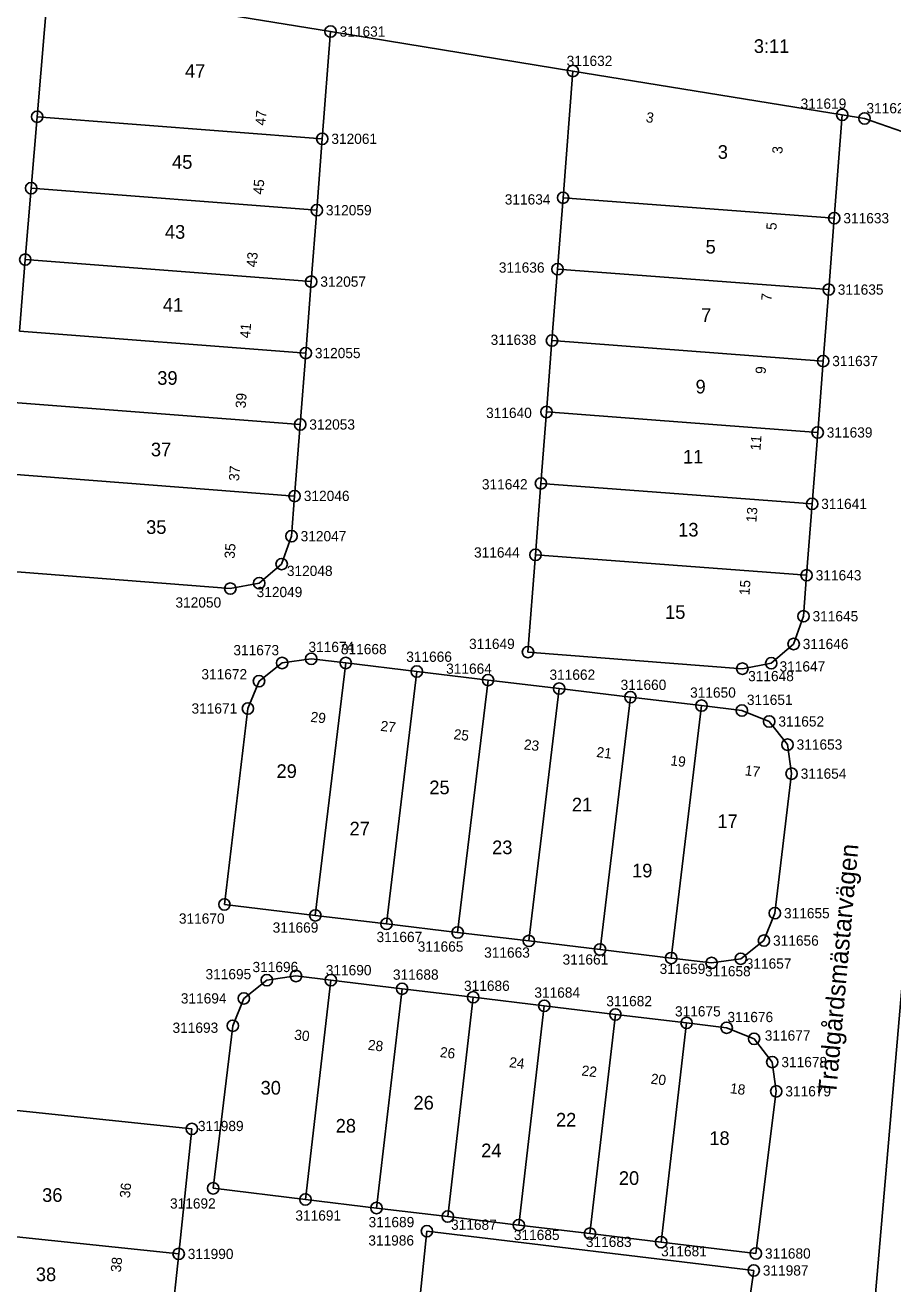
# Model space of a CAD drawing. Extents: x 141995 to 152570, y 6580184 to 6586000.
# Drawn here: x 142296 to 142372.2, y 6585066.5 to 6585177.1 of the extents above; entities that cross this region are included whole.
import ezdxf

# ---------------------------------------------------------------- set-up
doc = ezdxf.new("R2010")
doc.units = 0
for name, color, linetype in [('Level 10', 7, 'Continuous'), ('Level 43', 7, 'Continuous'), ('Level 5', 7, 'Continuous'), ('Level 51', 7, 'Continuous'), ('Level 53', 7, 'Continuous'), ('Level 54', 7, 'Continuous'), ('Level 55', 7, 'Continuous'), ('Level 6', 7, 'Continuous'), ('Level 7', 7, 'Continuous')]:
    doc.layers.add(name, color=color, linetype=linetype)

msp = doc.modelspace()

# ---------------------------------------------------------------- linework, layer by layer
at = {"layer": 'Level 10'}
for centre in [(142322.83, 6585176.58), (142344.13, 6585173.11), (142297.04, 6585169.09), (142367.8, 6585169.26), (142369.76, 6585168.94), (142322.1, 6585167.15), (142296.52, 6585162.81), (142343.26, 6585161.97), (142321.62, 6585160.87), (142367.1, 6585160.17), (142296, 6585156.53), (142342.78, 6585155.69), (142321.13, 6585154.59), (142366.61, 6585153.89), (142342.29, 6585149.41), (142320.65, 6585148.31), (142366.12, 6585147.61), (142341.81, 6585143.13), (142320.16, 6585142.03), (142365.64, 6585141.33), (142341.32, 6585136.85), (142319.67, 6585135.74), (142365.15, 6585135.05), (142319.4, 6585132.21), (142318.53, 6585129.76), (142340.84, 6585130.57), (142364.67, 6585128.77), (142314.02, 6585127.6), (142316.56, 6585128.08), (142364.39, 6585125.17), (142340.18, 6585122.02), (142363.53, 6585122.73), (142318.57, 6585121.06), (142321.13, 6585121.43), (142324.16, 6585121.06), (142361.56, 6585121.04), (142330.41, 6585120.31), (142359.02, 6585120.56), (142316.54, 6585119.46), (142336.67, 6585119.56), (142342.92, 6585118.81), (142349.18, 6585118.06), (142315.57, 6585117.06), (142355.43, 6585117.31), (142358.98, 6585116.88), (142361.38, 6585115.92), (142362.99, 6585113.88), (142363.35, 6585111.33), (142313.5, 6585099.83), (142321.49, 6585098.87), (142361.88, 6585099.06), (142327.75, 6585098.12), (142334, 6585097.37), (142340.26, 6585096.62), (142360.92, 6585096.65), (142346.51, 6585095.87), (142352.77, 6585095.12), (142356.32, 6585094.69), (142358.88, 6585095.06), (142319.79, 6585093.54), (142317.23, 6585093.17), (142322.85, 6585093.17), (142329.11, 6585092.42), (142315.21, 6585091.57), (142335.36, 6585091.67), (142341.61, 6585090.92), (142347.86, 6585090.16), (142314.24, 6585089.17), (142354.12, 6585089.41), (142357.64, 6585088.99), (142360.05, 6585088.02), (142361.65, 6585085.97), (142362, 6585083.4), (142310.64, 6585080.09), (142312.51, 6585074.87), (142320.62, 6585073.89), (142326.87, 6585073.14), (142333.13, 6585072.39), (142331.3, 6585071.1), (142339.37, 6585071.64), (142345.63, 6585070.89), (142351.88, 6585070.14), (142309.48, 6585069.1), (142360.21, 6585069.14), (142360.02, 6585067.65)]:
    msp.add_circle(centre, 0.5, dxfattribs=at)
at = {"layer": 'Level 5'}
for points in [[(142298, 6585180.62), (142322.83, 6585176.58)], [(142322.83, 6585176.58), (142344.13, 6585173.11)], [(142344.13, 6585173.11), (142367.8, 6585169.26)], [(142367.8, 6585169.26), (142369.76, 6585168.94)], [(142369.76, 6585168.94), (142373.13, 6585167.75)], [(142376.84, 6585136.75), (142367.36, 6585026.44)]]:
    msp.add_lwpolyline(points, dxfattribs=at)
at = {"layer": 'Level 6'}
msp.add_lwpolyline([(142228.18, 6585027.1), (142249.62, 6585025.47), (142274.29, 6585023.58), (142278.9, 6585023.24), (142304.43, 6585021.29), (142325.88, 6585019.66), (142352.75, 6585017.61), (142356.64, 6585017.32), (142360.49, 6585017.78), (142363.88, 6585019.67), (142366.29, 6585022.71), (142367.36, 6585026.44), (142376.84, 6585136.75), (142377.99, 6585153.73), (142378.15, 6585158.76), (142377.61, 6585162.31), (142375.87, 6585165.44), (142373.13, 6585167.75), (142369.76, 6585168.94), (142367.8, 6585169.26), (142344.13, 6585173.11), (142322.83, 6585176.58), (142298, 6585180.62)], dxfattribs=at)
at = {"layer": 'Level 7'}
for points in [[(142298, 6585180.62), (142297.04, 6585169.09)], [(142322.1, 6585167.15), (142322.83, 6585176.58)], [(142344.13, 6585173.11), (142343.26, 6585161.97)], [(142297.04, 6585169.09), (142296.52, 6585162.81)], [(142297.04, 6585169.09), (142322.1, 6585167.15)], [(142367.1, 6585160.17), (142367.8, 6585169.26)], [(142321.62, 6585160.87), (142322.1, 6585167.15)], [(142296.52, 6585162.81), (142296, 6585156.53)], [(142296.52, 6585162.81), (142321.62, 6585160.87)], [(142343.26, 6585161.97), (142342.78, 6585155.69)], [(142367.1, 6585160.17), (142343.26, 6585161.97)], [(142321.13, 6585154.59), (142321.62, 6585160.87)], [(142366.61, 6585153.89), (142367.1, 6585160.17)], [(142296, 6585156.53), (142295.48, 6585150.25)], [(142296, 6585156.53), (142321.13, 6585154.59)], [(142342.78, 6585155.69), (142342.29, 6585149.41)], [(142366.61, 6585153.89), (142342.78, 6585155.69)], [(142320.65, 6585148.31), (142321.13, 6585154.59)], [(142366.12, 6585147.61), (142366.61, 6585153.89)], [(142295.48, 6585150.25), (142320.65, 6585148.31)], [(142342.29, 6585149.41), (142341.81, 6585143.13)], [(142366.12, 6585147.61), (142342.29, 6585149.41)], [(142320.16, 6585142.03), (142320.65, 6585148.31)], [(142365.64, 6585141.33), (142366.12, 6585147.61)], [(142294.96, 6585143.97), (142320.16, 6585142.03)], [(142341.81, 6585143.13), (142341.32, 6585136.85)], [(142365.64, 6585141.33), (142341.81, 6585143.13)], [(142319.67, 6585135.74), (142320.16, 6585142.03)], [(142365.15, 6585135.05), (142365.64, 6585141.33)], [(142294.44, 6585137.69), (142319.67, 6585135.74)], [(142341.32, 6585136.85), (142340.84, 6585130.57)], [(142365.15, 6585135.05), (142341.32, 6585136.85)], [(142319.4, 6585132.21), (142319.67, 6585135.74)], [(142364.67, 6585128.77), (142365.15, 6585135.05)], [(142318.53, 6585129.76), (142319.4, 6585132.21)], [(142340.84, 6585130.57), (142340.18, 6585122.02)], [(142364.67, 6585128.77), (142340.84, 6585130.57)], [(142293.73, 6585129.18), (142314.02, 6585127.6)], [(142316.56, 6585128.08), (142318.53, 6585129.76)], [(142314.02, 6585127.6), (142316.56, 6585128.08)], [(142364.39, 6585125.17), (142364.67, 6585128.77)], [(142363.53, 6585122.73), (142364.39, 6585125.17)], [(142361.56, 6585121.04), (142363.53, 6585122.73)], [(142318.57, 6585121.06), (142321.13, 6585121.43)], [(142321.13, 6585121.43), (142324.16, 6585121.06)], [(142340.18, 6585122.02), (142359.02, 6585120.56)], [(142316.54, 6585119.46), (142318.57, 6585121.06)], [(142321.49, 6585098.87), (142324.16, 6585121.06)], [(142324.16, 6585121.06), (142330.41, 6585120.31)], [(142327.75, 6585098.12), (142330.41, 6585120.31)], [(142330.41, 6585120.31), (142336.67, 6585119.56)], [(142359.02, 6585120.56), (142361.56, 6585121.04)], [(142315.57, 6585117.06), (142316.54, 6585119.46)], [(142334, 6585097.37), (142336.67, 6585119.56)], [(142336.67, 6585119.56), (142342.92, 6585118.81)], [(142340.26, 6585096.62), (142342.92, 6585118.81)], [(142342.92, 6585118.81), (142349.18, 6585118.06)], [(142346.51, 6585095.87), (142349.18, 6585118.06)], [(142349.18, 6585118.06), (142355.43, 6585117.31)], [(142313.5, 6585099.83), (142315.57, 6585117.06)], [(142352.77, 6585095.12), (142355.43, 6585117.31)], [(142355.43, 6585117.31), (142358.98, 6585116.88)], [(142358.98, 6585116.88), (142361.38, 6585115.92)], [(142361.38, 6585115.92), (142362.99, 6585113.88)], [(142362.99, 6585113.88), (142363.35, 6585111.33)], [(142363.35, 6585111.33), (142361.88, 6585099.06)], [(142321.49, 6585098.87), (142313.5, 6585099.83)], [(142327.75, 6585098.12), (142321.49, 6585098.87)], [(142361.88, 6585099.06), (142360.92, 6585096.65)], [(142334, 6585097.37), (142327.75, 6585098.12)], [(142340.26, 6585096.62), (142334, 6585097.37)], [(142346.51, 6585095.87), (142340.26, 6585096.62)], [(142360.92, 6585096.65), (142358.88, 6585095.06)], [(142352.77, 6585095.12), (142346.51, 6585095.87)], [(142356.32, 6585094.69), (142352.77, 6585095.12)], [(142358.88, 6585095.06), (142356.32, 6585094.69)], [(142315.21, 6585091.57), (142317.23, 6585093.17)], [(142317.23, 6585093.17), (142319.79, 6585093.54)], [(142319.79, 6585093.54), (142322.85, 6585093.17)], [(142320.62, 6585073.89), (142322.85, 6585093.17)], [(142322.85, 6585093.17), (142329.11, 6585092.42)], [(142314.24, 6585089.17), (142315.21, 6585091.57)], [(142326.87, 6585073.14), (142329.11, 6585092.42)], [(142329.11, 6585092.42), (142335.36, 6585091.67)], [(142333.13, 6585072.39), (142335.36, 6585091.67)], [(142335.36, 6585091.67), (142341.61, 6585090.92)], [(142339.37, 6585071.64), (142341.61, 6585090.92)], [(142341.61, 6585090.92), (142347.86, 6585090.16)], [(142345.63, 6585070.89), (142347.86, 6585090.16)], [(142347.86, 6585090.16), (142354.12, 6585089.41)], [(142351.88, 6585070.14), (142354.12, 6585089.41)], [(142354.12, 6585089.41), (142357.64, 6585088.99)], [(142312.51, 6585074.87), (142314.24, 6585089.17)], [(142357.64, 6585088.99), (142360.05, 6585088.02)], [(142360.05, 6585088.02), (142361.65, 6585085.97)], [(142361.65, 6585085.97), (142362, 6585083.4)], [(142310.64, 6585080.09), (142285.17, 6585082.78)], [(142362, 6585083.4), (142360.21, 6585069.14)], [(142309.48, 6585069.1), (142310.64, 6585080.09)], [(142320.62, 6585073.89), (142312.51, 6585074.87)], [(142326.87, 6585073.14), (142320.62, 6585073.89)], [(142333.13, 6585072.39), (142326.87, 6585073.14)], [(142309.48, 6585069.1), (142284.01, 6585071.78)], [(142339.37, 6585071.64), (142333.13, 6585072.39)], [(142345.63, 6585070.89), (142339.37, 6585071.64)], [(142331.3, 6585071.1), (142330.38, 6585062.29)], [(142360.02, 6585067.65), (142331.3, 6585071.1)], [(142351.88, 6585070.14), (142345.63, 6585070.89)], [(142360.21, 6585069.14), (142351.88, 6585070.14)], [(142308.81, 6585062.84), (142309.48, 6585069.1)], [(142358.79, 6585059.18), (142360.02, 6585067.65)]]:
    msp.add_lwpolyline(points, dxfattribs=at)

# ---------------------------------------------------------------- texts
at = {"layer": 'Level 43'}
msp.add_text('Trädgårdsmästarvägen', height=1.6, rotation=84.8558, dxfattribs=at).set_placement((142367.25, 6585083.05))
at = {"layer": 'Level 51'}
for s, p in [('3:11', (142360.03, 6585174.7)), ('47', (142310.04, 6585172.51)), ('45', (142308.9, 6585164.51)), ('3', (142356.86, 6585165.39)), ('43', (142308.27, 6585158.36)), ('5', (142355.79, 6585157.06)), ('41', (142308.09, 6585151.94)), ('7', (142355.4, 6585151.05)), ('39', (142307.6, 6585145.52)), ('9', (142354.91, 6585144.76)), ('37', (142307.04, 6585139.23)), ('11', (142353.81, 6585138.6)), ('35', (142306.62, 6585132.41)), ('13', (142353.38, 6585132.18)), ('15', (142352.23, 6585124.94)), ('29', (142318.08, 6585110.95)), ('25', (142331.51, 6585109.52)), ('21', (142344.04, 6585108.01)), ('27', (142324.5, 6585105.9)), ('17', (142356.83, 6585106.55)), ('23', (142337.03, 6585104.25)), ('19', (142349.33, 6585102.21)), ('30', (142316.68, 6585083.11)), ('26', (142330.12, 6585081.8)), ('22', (142342.64, 6585080.3)), ('28', (142323.28, 6585079.77)), ('18', (142356.12, 6585078.68)), ('24', (142336.07, 6585077.6)), ('20', (142348.17, 6585075.17)), ('36', (142297.48, 6585073.68)), ('38', (142296.93, 6585066.71))]:
    msp.add_text(s, height=1.2, rotation=0.0522, dxfattribs=at).set_placement(p)
at = {"layer": 'Level 53'}
for s, p in [('311631', (142323.63, 6585176.13)), ('311632', (142343.58, 6585173.55)), ('311619', (142364.14, 6585169.79)), ('311620', (142369.93, 6585169.39)), ('312061', (142322.9, 6585166.7)), ('312059', (142322.42, 6585160.42)), ('311634', (142338.14, 6585161.37)), ('311633', (142367.9, 6585159.72)), ('311636', (142337.62, 6585155.38)), ('312057', (142321.93, 6585154.14)), ('311635', (142367.41, 6585153.44)), ('311638', (142336.9, 6585149.03)), ('312055', (142321.45, 6585147.86)), ('311637', (142366.92, 6585147.16)), ('311640', (142336.5, 6585142.6)), ('312053', (142320.96, 6585141.58)), ('311639', (142366.44, 6585140.88)), ('311642', (142336.13, 6585136.32)), ('312046', (142320.48, 6585135.3)), ('311641', (142365.95, 6585134.6)), ('312047', (142320.2, 6585131.76)), ('311644', (142335.44, 6585130.33)), ('312048', (142318.99, 6585128.71)), ('311643', (142365.47, 6585128.32)), ('312049', (142316.33, 6585126.85)), ('312050', (142309.2, 6585125.93)), ('311645', (142365.19, 6585124.72)), ('311673', (142314.29, 6585121.74)), ('311674', (142320.89, 6585122.02)), ('311668', (142323.74, 6585121.83)), ('311649', (142335, 6585122.29)), ('311646', (142364.33, 6585122.28)), ('311666', (142329.48, 6585121.16)), ('311672', (142311.48, 6585119.62)), ('311664', (142332.99, 6585120.11)), ('311662', (142342.07, 6585119.58)), ('311648', (142359.53, 6585119.46)), ('311647', (142362.29, 6585120.31)), ('311660', (142348.32, 6585118.69)), ('311650', (142354.43, 6585118.01)), ('311651', (142359.42, 6585117.37)), ('311671', (142310.61, 6585116.61)), ('311652', (142362.19, 6585115.47)), ('311653', (142363.79, 6585113.44)), ('311654', (142364.15, 6585110.88)), ('311655', (142362.68, 6585098.61)), ('311670', (142309.5, 6585098.14)), ('311669', (142317.74, 6585097.35)), ('311667', (142326.87, 6585096.52)), ('311656', (142361.72, 6585096.2)), ('311665', (142330.49, 6585095.68)), ('311663', (142336.33, 6585095.15)), ('311661', (142343.22, 6585094.54)), ('311657', (142359.32, 6585094.18)), ('311695', (142311.84, 6585093.25)), ('311696', (142315.97, 6585093.88)), ('311690', (142322.41, 6585093.6)), ('311688', (142328.31, 6585093.21)), ('311659', (142351.75, 6585093.72)), ('311658', (142355.74, 6585093.51)), ('311686', (142334.56, 6585092.23)), ('311694', (142309.67, 6585091.12)), ('311684', (142340.74, 6585091.63)), ('311682', (142347.06, 6585090.88)), ('311675', (142353.1, 6585089.98)), ('311676', (142357.71, 6585089.48)), ('311693', (142308.94, 6585088.54)), ('311677', (142360.99, 6585087.86)), ('311678', (142362.45, 6585085.52)), ('311679', (142362.8, 6585082.95)), ('311989', (142311.17, 6585079.9)), ('311692', (142308.72, 6585073.09)), ('311691', (142319.74, 6585072.03)), ('311689', (142326.17, 6585071.45)), ('311687', (142333.42, 6585071.22)), ('311986', (142326.15, 6585069.84)), ('311685', (142338.94, 6585070.32)), ('311683', (142345.27, 6585069.71)), ('311990', (142310.28, 6585068.65)), ('311681', (142351.88, 6585068.89)), ('311680', (142361.01, 6585068.69)), ('311987', (142360.82, 6585067.2))]:
    msp.add_text(s, height=0.9, rotation=0.0522, dxfattribs=at).set_placement(p)
at = {"layer": 'Level 54'}
for s, rotation, p in [('47', 85.5788, (142317.1, 6585168.29)), ('3', 85.6848, (142362.53, 6585165.8)), ('45', 85.5888, (142316.91, 6585162.22)), ('5', 85.6858, (142362.01, 6585159.1)), ('43', 85.5888, (142316.33, 6585155.82)), ('7', 85.6938, (142361.57, 6585152.87)), ('41', 85.5788, (142315.75, 6585149.58)), ('9', 85.6928, (142361.06, 6585146.44)), ('39', 85.5888, (142315.36, 6585143.43)), ('11', 85.6818, (142360.61, 6585139.72)), ('37', 85.5888, (142314.78, 6585137.03)), ('13', 85.6828, (142360.25, 6585133.4)), ('35', 85.5888, (142314.39, 6585130.21)), ('15', 85.6848, (142359.64, 6585126.99)), ('29', 353.156, (142321.03, 6585115.9)), ('27', 353.164, (142327.18, 6585115.1)), ('25', 353.152, (142333.61, 6585114.37)), ('23', 353.155, (142339.78, 6585113.47)), ('21', 353.164, (142346.16, 6585112.8)), ('19', 353.155, (142352.66, 6585112.07)), ('17', 353.153, (142359.2, 6585111.19)), ('30', 353.101, (142319.6, 6585087.95)), ('28', 353.105, (142326.07, 6585087.06)), ('26', 353.096, (142332.4, 6585086.42)), ('24', 353.097, (142338.49, 6585085.53)), ('22', 353.096, (142344.85, 6585084.8)), ('20', 353.103, (142350.93, 6585084.08)), ('18', 353.103, (142357.9, 6585083.24)), ('36', 83.9728, (142305.18, 6585073.98)), ('38', 83.9818, (142304.39, 6585067.45))]:
    msp.add_text(s, height=0.9, rotation=rotation, dxfattribs=at).set_placement(p)
at = {"layer": 'Level 55'}
msp.add_text('3', height=0.9, rotation=350.766, dxfattribs=at).set_placement((142350.5, 6585168.63))

doc.saveas('drawing.dxf')
